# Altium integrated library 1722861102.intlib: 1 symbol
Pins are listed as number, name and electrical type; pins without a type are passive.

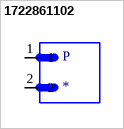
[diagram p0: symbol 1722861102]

## 1722861102
designator P
Connector Header Through Hole 2 position 0.138 _3.50mm_; MP: 1722861102; MF: Molex
footprint MOLEX_1722861102
pins: 1, 2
